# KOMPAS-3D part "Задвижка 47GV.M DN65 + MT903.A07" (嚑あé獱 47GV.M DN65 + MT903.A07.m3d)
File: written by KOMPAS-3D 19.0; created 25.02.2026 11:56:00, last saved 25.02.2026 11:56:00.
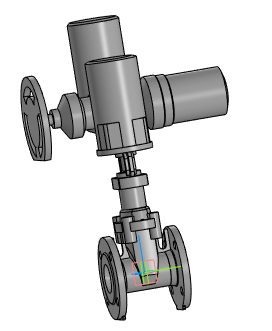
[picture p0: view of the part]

Document properties: Автор: Евгений; Полное имя файла: 47 GV.M DN50\Задвижка 47GV.M DN50 с переходом под ISO фланец.a3d

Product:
- Part/product: Задвижка 47GV.M DN65 + MT903.A07
    Масса: 82.5167
    Раздел спецификации: Документация
    Форматы листов документа: 2xA3
  - Component: Задвижка с обрезиненным клином DN50. Сборочный чертеж  | designation DR.47GVM.050.16.00.000СБ  | pos. 0  | Масса: 10.0548; Раздел спецификации: Документация; Форматы листов документа: 2xA3; source file: 47GV.M DN65\DR.47GVM.050.16.00.000 СБ - Задвижка с обрезиненным клином DN100.cdw
- Part/product: Задвижка 47GV.M DN65 + MT903.A07  | designation 01
    Масса: 10.055
  - Component [detail]: Шпиндель  | pos. 5  | Материал: Сталь 20Х13 ГОСТ 5632-2014 (density 7670 kg/m3); Масса: 0.101759; Раздел спецификации: Детали; source file: 47GV.M DN50\DR.47GVM.050.16.00.003 - Шпиндель.cdw, 47GV.M DN65\DR.47GVM.050.16.00.003 - Шпиндель.cdw, 47GV.M DN65\Шпиндель 47GV.M DN50.m3d
  - Component [detail]: Крышка DN65  | pos. 4  | Материал: ВЧ50 ГОСТ 7293-85 (density 7200 kg/m3); Масса: 3.48496; Раздел спецификации: Детали; Форматы листов документа: 2xA3; source file: 47GV.M DN65\DR.47GVM.050.16.00.002 - Крышка.cdw, 47GV.M DN65\DR.47GVM.065.16.00.002 - Крышка.cdw, 47GV.M DN65\Крышка 47GV.M DN50.m3d
  - Component [assembly]: Клин с направляющими  | designation DR.47GVM.050.16.01.000  | pos. 4  | Раздел спецификации: Сборочные единицы; Форматы листов документа: A4; source file: 47GV.M DN65\DR.47GVM.050.16.01.000  - Клин с направляющими.a3d, 47GV.M DN65\DR.47GVM.050.16.01.000  - Клин с направляющими.spw, 47GV.M DN65\DR.47GVM.050.16.01.000  СБ - Клин с направляющими.cdw
  - Component [detail]: Корпус  | designation DR.47GVM.065.16.00.001  | pos. 3  | Материал: ВЧ50 ГОСТ 7293-85 (density 7200 kg/m3); Масса: 11.3996; Раздел спецификации: Детали; Форматы листов документа: 2xA3; source file: 47GV.M DN65\DR.47GVM.050.16.00.001 - Корпус.cdw, 47GV.M DN65\Корпус 47GV.M DN50.m3d
  - Component [detail]: Стойка  | pos. 44  | Материал: ВЧ50 ГОСТ 7293-85 (density 7200 kg/m3); Масса: 1.73762; Раздел спецификации: Детали; Форматы листов документа: 2xA3; source file: 47GV.M DN50\DR.47GVAM.050.16.00.001 - Стойка.cdw, 47GV.M DN65\Стойка DN50.m3d
  - Component [detail]: Удлинитель шпинделя  | pos. 45  | Материал: Сталь 20Х13 ГОСТ 5632-72 (density 7670 kg/m3); Масса: 0.307911; Раздел спецификации: Детали; source file: 47GV.M DN50\DR.47GVAM.050.16.00.002 - Удлинитель шпинделя.cdw, 47GV.M DN65\Удлинитель шпинделя DN50.m3d
  - Component: Электропривод МТ903.А07 без блока управления  | Масса: 65.4738; source file: 47GV.M DN50\Электропривод МТ903.А07 без блока управления.m3d

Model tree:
1. Операция без истории:1

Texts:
  Точка начала. Х
  Точка начала. Y
  Точка начала. Z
